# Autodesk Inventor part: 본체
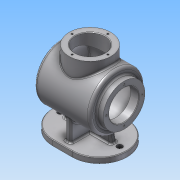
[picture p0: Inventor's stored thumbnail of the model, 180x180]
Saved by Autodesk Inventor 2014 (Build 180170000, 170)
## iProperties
Created: 2016-04
Part Number: 본체
Material: 알루미늄 6061
Document SubType Name: Modeling
Designer: 601-
Density: 2.71 g/cm^3
Appearance: 알루미늄 - 평지
Mass: 916.104 g
Surface Area: 1236.98 cm^2
Volume: 338.046 cm^3
Author: 601-
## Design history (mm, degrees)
sketch "스케치1"
  geometry: L1 (-67.5, -50)-(67.5, -50); L2 (67.5, -50)-(67.5, 50); L3 (67.5, 50)-(-67.5, 50); L4 (-67.5, 50)-(-67.5, -50); L5 (-67.5, -50)-(67.5, 50); L6 (67.5, -50)-(-67.5, 50); 1 further point
  constraints: 12 end point, 2 midpoint, 2 parallel, 1 horizontal, 1 perpendicular
  dimensions: "d0" = 135 distance of L2.end L3.end; "d1" = 100 distance of L3.end L1.start
extrude "돌출1" new body sketch "스케치1" distance "d2" = 10; taper "d3" = 0 deg
fillet "모깎기1"
fillet "모깎기2"
sketch "스케치2"
  geometry: L1 (-5, -40)-(5, -40); L2 (5, -40)-(5, 40); L3 (5, 40)-(-5, 40); L4 (-5, 40)-(-5, -40); L5 (-5, -40)-(5, 40); L6 (5, -40)-(-5, 40); 2 further points
  constraints: 12 end point, 2 midpoint, 2 parallel, 1 coincident, 1 horizontal, 1 perpendicular
  dimensions: "d6" = 10 distance of L2.end L3.end; "d7" = 80 distance of L1.end L2.end
extrude "돌출2" join sketch "스케치2" distance "d8" = 69; taper "d9" = 0 deg
sketch "스케치26"
  geometry: L1 (17.5, 50)-(-17.5, 50) reference; L2 (-17.5, -50)-(17.5, -50) reference; L3 (-54, 0)-(54, 0); L4 (0, 50)-(0, -50); C1 r 5 at (-54, 0); C2 r 5 at (54, 0); 2 further points
  constraints: 4 end point, 3 coincident, 3 midpoint, 2 centre point, 1 parallel
  dimensions: "d102" = 108 distance of L3.start L3.end; "d103" = 10 diameter of C1; "d104" = 10 diameter of C2
extrude "돌출9" cut sketch "스케치26" stored distance "d105" = 10; taper "d106" = 0 deg
sketch "스케치23"
  geometry: L1 (0, -5)-(40, -5); L2 (40, -5)-(40, 5); L3 (40, 5)-(0, 5); L4 (-40, -5)-(40, 5); L5 (40, -5)-(-40, 5); L6 (0, 5)-(0, -5); 1 further point
  constraints: 12 end point, 2 midpoint, 1 horizontal, 1 parallel, 1 perpendicular
  dimensions: "d81" = 10 distance of L1.end L2.end; "d91" = 40 distance of L2.end L3.end
sketch "스케치4"
  geometry: L1 (-50, 0)-(-50, 10) reference; L2 (-50, 10)-(-40, 10) reference; L3 (-40, 10)-(-40, 79) reference; L4 (-40, 79)-(40, 79) reference; L5 (40, 79)-(40, 10) reference; L6 (40, 10)-(50, 10) reference; L7 (50, 10)-(50, 0) reference; L8 (50, 0)-(-50, 0) reference; L9 (0, 0)-(0, 79); C1 r 50 at (0, 79)
  constraints: 2 end point, 1 centre point, 1 coincident, 1 midpoint
  dimensions: "d15" = 100 diameter of C1
extrude "돌출3" join sketch "스케치4" stored distance "d16" = 100; taper "d17" = 0 deg
sketch "스케치5"
  geometry: C1 r 50 at (0, 0) reference; C2 r 38 at (0, 0); 1 further point
  constraints: 1 centre point, 1 coincident
  dimensions: "d18" = 76 diameter of C2
extrude "돌출4" join sketch "스케치5" distance "d19" = 12; taper "d20" = 0 deg
sketch "스케치6"
  geometry: L1 (-62, 117)-(-62, 41) reference; L2 (-62, 79)-(60.654, 79); L3 (50, 29)-(50, 129) reference; L4 (50, 129)-(50, 79); L5 (50, 79)-(60.654, 79); L6 (50, 129)-(50, 79); A1 r 122.654 centre (-62, 79) between (60.654, 79) and (50, 129); 1 further point
  constraints: 8 end point, 2 midpoint, 2 point on circle, 1 centre point, 1 coincident, 1 collinear, 1 perpendicular
revolve "회전2" sketch "스케치6" stored, may be unused: angle "d22" = 90 deg
sketch "스케치11"
  geometry: L1 (50, 29)-(-50, 29) reference; L2 (-5, 10)-(-5, 49) reference; L3 (-17.5, 10)-(17.5, 10) reference; L4 (-67.5, 10)-(-17.5, 10) reference; L5 (0, 0)-(0, 62.75); L6 (-17.5, 0)-(17.5, 0) reference; L7 (-67.5, 0)-(-67.5, 10) reference; L8 (-49, 10)-(-5, 10) reference; L9 (-5, 10)-(-5, 29) reference; L10 (-5, 29)-(-50, 29) reference; L11 (-50, 29)-(-50, 41) reference; L12 (-50, 41)-(-62, 41) reference; L13 (-62, 41)-(-62, 117) reference; L14 (-62, 117)-(-50, 117) reference; L15 (-50, 117)-(-50, 129) reference; L16 (-50, 129)-(50, 129) reference; L17 (50, 29)-(5, 29) reference; L18 (5, 29)-(5, 10) reference; L19 (59, 10)-(67.5, 10) reference; L20 (67.5, 10)-(67.5, 0) reference; L21 (67.5, 0)-(59, 0) reference; L22 (-40, 10)-(-36.65, 29); L23 (59, 0)-(59, 10) reference; L24 (-49, 0)-(-49, 10) reference; L25 (5, 10)-(49, 10) reference; L26 (49, 10)-(49, 0) reference; L27 (49, 0)-(-49, 0) reference; L28 (-67.5, 10)-(-59, 10) reference; L29 (-59, 10)-(-59, 0) reference; L30 (-59, 0)-(-67.5, 0) reference; A1 r 122.654 centre (-62, 79) between (50, 29) and (50, 129) reference
  constraints: 4 end point, 2 point on line, 1 perpendicular
  dimensions: "d33" = 100 deg angle of L8 L22; "d34" = 40 horizontal distance of L5.start L22.start
  node "절단 모서리 투영4"
node "작업 평면2"
sketch "스케치13"
  geometry: C1 r 38 at (0, 0); 1 further point
  constraints: 1 centre point, 1 coincident
  dimensions: "d38" = 76 diameter of C1
extrude "돌출6" join sketch "스케치13" stored distance "d39" = 10; taper "d40" = 0 deg
sketch "스케치14"
  geometry: C1 r 38 at (0, 0) reference; C2 r 27 at (0, 0)
  constraints: 1 centre point, 1 coincident
  dimensions: "d41" = 54 diameter of C2
sketch "스케치19"
  geometry: L1 (-38, 144)-(-38, 129) reference; L2 (-38, 144)-(38, 144) reference; L3 (50, 129)-(-50, 129) reference; L4 (38, 144)-(38, 129) reference; L5 (-50, 129)-(-50, 29) reference; L6 (48.037, 126)-(-47, 126); L7 (-47, 126)-(-47, 79); L8 (-62, 79)-(57.654, 79); L9 (-62, 79)-(-47, 79); L10 (-47, 79)-(-47, 106); L11 (-47, 106)-(-62, 106); L12 (-62, 106)-(-62, 79); A1 r 122.654 centre (-62, 79) between (50, 29) and (50, 129) reference; A2 r 119.654 centre (-62, 79) between (57.654, 79) and (48.037, 126); 1 further point
  constraints: 14 end point, 2 parallel, 2 point on circle, 1 centre point, 1 horizontal, 1 perpendicular, 1 point on line
  dimensions: "d47" = 3 radial gap between concentric circles of A1 A2; "d48" = 3 distance between parallel lines of L3 L6; "d51" = 27 distance of L11.end L8.start
revolve "회전3" sketch "스케치19" stored, may be unused: angle "d49" = 90 deg
sketch "스케치20" dims "d50" = 65
  geometry: L1 (0, 0)-(-32.5, 0); C1 r 38 at (0, 0) reference; 2 further points
  constraints: 2 coincident, 2 end point, 1 horizontal, 1 horizontal alignment, 2 other
hole "구멍1" sketch "스케치20" at (-32.5, 0) diameter "d52" = 3.242; stored, may be unused: countersink angle "d56" = 90 deg, drill point angle "d58" = 118 deg; dims "d53" = 8, "d54" = 4, "d55" = 2, "d57" = 10
extrude "돌출7" cut sketch "스케치14" stored distance "d62" = 10; taper "d63" = 0 deg
sketch "스케치21" dims "d64" = 65
  geometry: L1 (0, 0)-(0, 32.5); C1 r 38 at (0, 0) reference; 1 further point
  constraints: 2 coincident, 2 end point, 1 vertical, 1 vertical alignment, 2 other
hole "구멍2" sketch "스케치21" at (0, 32.5) diameter "d65" = 3.242; stored, may be unused: countersink angle "d69" = 90 deg, drill point angle "d71" = 118 deg; dims "d66" = 8, "d67" = 4, "d68" = 2, "d70" = 10
fillet "모깎기6" dims "d76" = 5
fillet "모깎기7" dims "d77" = 3
extrude "돌출8" join sketch "스케치23" stored distance "d82" = 10; taper "d83" = 0 deg
feature "면 기울기5" dims angle "d88" = 10 deg
sketch "스케치25"
  geometry: 1 further point
fillet "모깎기8" dims "d92" = 2
fillet "모깎기9" dims "d93" = 3
fillet "모깎기10" dims "d94" = 3
fillet "모깎기11" dims "d95" = 3
chamfer "모따기1" distance "d96" = 1; stored, may be unused: second distance "d97" = 2, angle "d98" = 45 deg
chamfer "모따기2" distance "d99" = 1; stored, may be unused: second distance "d100" = 2, angle "d101" = 45 deg
fillet "모깎기12" dims "d110" = 3
chamfer "모따기3" distance "d111" = 1; stored, may be unused: second distance "d112" = 2, angle "d113" = 45 deg
node "작업 평면10"
sketch "스케치33"
  geometry: 2 further points
  constraints: 1 other
  dimensions: "d122" = 79 vertical distance of point (0, 0) point (-0.618, 79)
feature "엠보싱1" sketch "스케치33" dims "d120" = 1, "d121" = 0
node "솔리드1"
pattern_circular "원형 패턴1" dims angle "d60" = 360 deg
pattern_circular "원형 패턴2" dims angle "d73" = 360 deg
mirror "대칭2"
node "절단 모서리 투영2"
other parameters: "d37" = 144, "d119" = -74
